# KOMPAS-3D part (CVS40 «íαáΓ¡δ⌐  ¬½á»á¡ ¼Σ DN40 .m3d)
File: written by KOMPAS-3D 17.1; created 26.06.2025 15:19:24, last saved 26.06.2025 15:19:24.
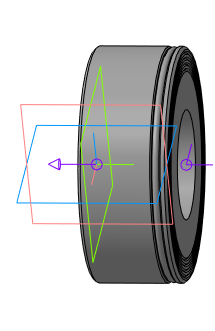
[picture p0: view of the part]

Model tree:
1. Эскиз:1
2. Элемент вращения:1
     Угол 1 = 360
3. Присоединительная точка:1
4. Присоединительная точка:2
